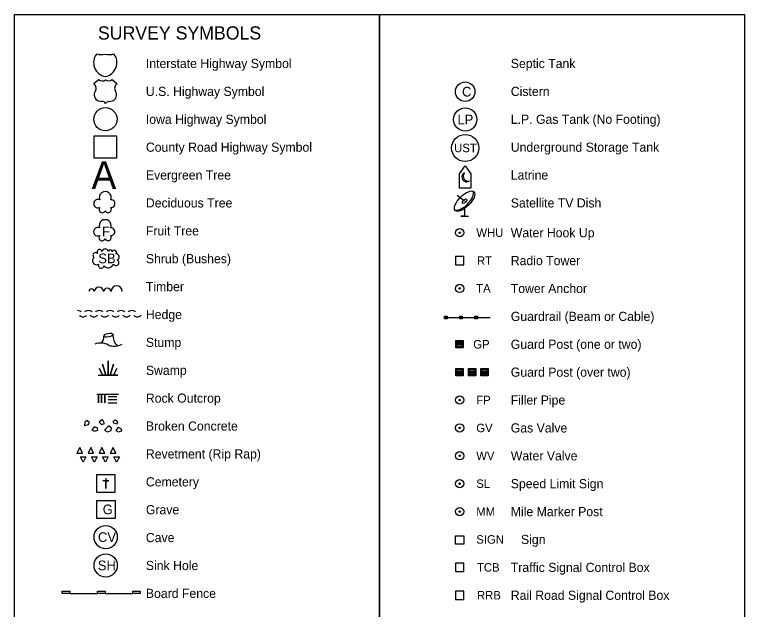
# Model space of a CAD drawing. Extents: x 6082259 to 6083454, y 5964102 to 5966092.
# Drawn here: x 6082259 to 6083454, y 5965119 to 5966092 of the extents above; entities that cross this region are included whole.
import ezdxf

# ---------------------------------------------------------------- set-up
doc = ezdxf.new("R2010")
doc.units = 0
for name, color, linetype in [('Default', 7, 'Continuous'), ('Level 20', 7, 'Continuous'), ('Text', 7, 'Continuous')]:
    doc.layers.add(name, color=color, linetype=linetype)

msp = doc.modelspace()

# ---------------------------------------------------------------- linework, layer by layer
at = {"layer": 'Default'}
for points in [[(6082259, 5966092.2), (6082856.5, 5966092.2), (6082856.5, 5964102.2), (6082259, 5964102.2)], [(6082856.5, 5966092.2), (6083454, 5966092.2), (6083454, 5964102.2), (6082856.5, 5964102.2)]]:
    msp.add_lwpolyline(points, close=True, dxfattribs=at)
at = {"layer": 'Level 20'}
for p, q in [((6082407.8, 5966012.2), (6082407.8, 5966012.2)), ((6082388.5, 5965978.8), (6082396.6, 5965986)), ((6082418.8, 5965985.9), (6082426.9, 5965978.7)), ((6082391, 5965966.7), (6082391.4, 5965967.3)), ((6082407.8, 5965966.5), (6082407.8, 5965966.5)), ((6082396.7, 5965951), (6082396, 5965951.3)), ((6082402.5, 5965950.1), (6082401.5, 5965950.1)), ((6082407.8, 5965920.9), (6082407.8, 5965920.9)), ((6082995.9, 5965786.9), (6082983.5, 5965796.2)), ((6082412.3, 5965467.3), (6082426.5, 5965467.3)), ((6082412.3, 5965462), (6082426.5, 5965462)), ((6082412.3, 5965456.6), (6082426.5, 5965456.6))]:
    msp.add_line(p, q, dxfattribs=at)
for points in [[(6082389.5, 5965893.5), (6082426, 5965893.5), (6082426, 5965857), (6082389.5, 5965857), (6082389.5, 5965893.5)], [(6082987.8, 5965808.3), (6082987.8, 5965831.8), (6082996.9, 5965844.5), (6083005.9, 5965831.8), (6083005.9, 5965808.3), (6082987.8, 5965808.3)], [(6082995.9, 5965774.5), (6082995.9, 5965762.1), (6082989.7, 5965762.1), (6083002.1, 5965762.1)], [(6082987.8, 5965682.8), (6082987.8, 5965682.8), (6082994.6, 5965682.8), (6082994.6, 5965696.4), (6082981, 5965696.4), (6082981, 5965682.8), (6082987.8, 5965682.8)], [(6082963.2, 5965594.3), (6082963.2, 5965598.4), (6082967.3, 5965598.4), (6082967.3, 5965594.3), (6082963.2, 5965594.3), (6082963.2, 5965595.7), (6082967.3, 5965595.7), (6082967.3, 5965597), (6082963.2, 5965597)], [(6082963.2, 5965596.4), (6083037.5, 5965596.4)], [(6082988, 5965594.3), (6082988, 5965598.4), (6082992.1, 5965598.4), (6082992.1, 5965594.3), (6082988, 5965594.3), (6082988, 5965595.7), (6082992.1, 5965595.7), (6082992.1, 5965597), (6082988, 5965597)], [(6083012.7, 5965594.3), (6083012.7, 5965598.4), (6083016.9, 5965598.4), (6083016.9, 5965594.3), (6083012.7, 5965594.3), (6083012.7, 5965595.7), (6083016.9, 5965595.7), (6083016.9, 5965597), (6083012.7, 5965597)], [(6082982.8, 5965547.7), (6082982.8, 5965557.6), (6082992.7, 5965557.6), (6082992.7, 5965547.7), (6082982.8, 5965547.7), (6082982.8, 5965549.7), (6082992.7, 5965549.7), (6082992.7, 5965551.7), (6082982.8, 5965551.7), (6082982.8, 5965553.7), (6082992.7, 5965553.7), (6082992.7, 5965555.6), (6082982.8, 5965555.6)], [(6082396, 5965502.1), (6082428.1, 5965502.1), (6082421, 5965502.1), (6082426.3, 5965512.8), (6082421, 5965502.1), (6082415.6, 5965502.1), (6082421, 5965520), (6082415.6, 5965502.1), (6082412.1, 5965502.1), (6082412.1, 5965525.3), (6082412.1, 5965502.1), (6082408.5, 5965502.1), (6082403.2, 5965520), (6082408.5, 5965502.1), (6082403.2, 5965502.1), (6082397.8, 5965512.8), (6082403.2, 5965502.1)], [(6082982.8, 5965502.1), (6082982.8, 5965512), (6082992.7, 5965512), (6082992.7, 5965502.1), (6082982.8, 5965502.1), (6082982.8, 5965504.1), (6082992.7, 5965504.1), (6082992.7, 5965506), (6082982.8, 5965506), (6082982.8, 5965508), (6082992.7, 5965508), (6082992.7, 5965510), (6082982.8, 5965510)], [(6083003.2, 5965502.1), (6083003.2, 5965512), (6083013.1, 5965512), (6083013.1, 5965502.1), (6083003.2, 5965502.1), (6083003.2, 5965504.1), (6083013.1, 5965504.1), (6083013.1, 5965506), (6083003.2, 5965506), (6083003.2, 5965508), (6083013.1, 5965508), (6083013.1, 5965510), (6083003.2, 5965510)], [(6083023.5, 5965502.1), (6083023.5, 5965512), (6083033.4, 5965512), (6083033.4, 5965502.1), (6083023.5, 5965502.1), (6083023.5, 5965504.1), (6083033.4, 5965504.1), (6083033.4, 5965506), (6083023.5, 5965506), (6083023.5, 5965508), (6083033.4, 5965508), (6083033.4, 5965510), (6083023.5, 5965510)], [(6082393.5, 5965470.9), (6082396.2, 5965470.9), (6082396.2, 5965456.6), (6082396.2, 5965470.9), (6082401.6, 5965470.9), (6082401.6, 5965456.6), (6082401.6, 5965470.9), (6082406.9, 5965470.9), (6082406.9, 5965456.6), (6082406.9, 5965470.9), (6082429.2, 5965470.9)], [(6082361, 5965374.6), (6082370.2, 5965374.6), (6082365.6, 5965383.8), (6082361, 5965374.6)], [(6082379.3, 5965374.6), (6082388.4, 5965374.6), (6082383.9, 5965383.8), (6082379.3, 5965374.6)], [(6082397.6, 5965374.6), (6082406.7, 5965374.6), (6082402.1, 5965383.8), (6082397.6, 5965374.6)], [(6082415.8, 5965374.6), (6082424.9, 5965374.6), (6082420.4, 5965383.8), (6082415.8, 5965374.6)], [(6082366.7, 5965368.6), (6082375.8, 5965368.6), (6082371.2, 5965359.5), (6082366.7, 5965368.6)], [(6082384.9, 5965368.6), (6082394.1, 5965368.6), (6082389.5, 5965359.5), (6082384.9, 5965368.6)], [(6082403.2, 5965368.6), (6082412.3, 5965368.6), (6082407.8, 5965359.5), (6082403.2, 5965368.6)], [(6082421.5, 5965368.6), (6082430.6, 5965368.6), (6082426, 5965359.5), (6082421.5, 5965368.6)], [(6082393.8, 5965310.2), (6082393.8, 5965339.7), (6082423.4, 5965339.7), (6082423.4, 5965310.2), (6082393.8, 5965310.2)], [(6082408.6, 5965333.3), (6082408.6, 5965316.6), (6082408.6, 5965328.9), (6082413.5, 5965328.9), (6082403.7, 5965328.9)], [(6082987.8, 5965180.8), (6082987.8, 5965180.8), (6082994.6, 5965180.8), (6082994.6, 5965194.3), (6082981, 5965194.3), (6082981, 5965180.8), (6082987.8, 5965180.8)], [(6082349.4, 5965145), (6082395, 5965145)], [(6082407.2, 5965145), (6082452.8, 5965145)], [(6082464.9, 5965145), (6082464.9, 5965145)], [(6082987.8, 5965135.1), (6082987.8, 5965135.1), (6082994.6, 5965135.1), (6082994.6, 5965148.7), (6082981, 5965148.7), (6082981, 5965135.1), (6082987.8, 5965135.1)]]:
    msp.add_lwpolyline(points, dxfattribs=at)
for points in [[(6082981.8, 5965546.7), (6082981.8, 5965558.6), (6082993.7, 5965558.6), (6082993.7, 5965546.7)], [(6082981.8, 5965501.1), (6082981.8, 5965513), (6082993.7, 5965513), (6082993.7, 5965501.1)], [(6083002.2, 5965501.1), (6083002.2, 5965513), (6083014.1, 5965513), (6083014.1, 5965501.1)], [(6083022.5, 5965501.1), (6083022.5, 5965513), (6083034.4, 5965513), (6083034.4, 5965501.1)], [(6082401.7, 5965429), (6082397.3, 5965424.9), (6082401.5, 5965421.3), (6082406.4, 5965422.8), (6082404.3, 5965427.2)], [(6082423.7, 5965428.6), (6082419.9, 5965426.3), (6082421.1, 5965424.2), (6082427.1, 5965422.6), (6082427.9, 5965425.5)], [(6082376.8, 5965427.8), (6082374.2, 5965425.4), (6082373.7, 5965419.7), (6082380.2, 5965421.3), (6082381.5, 5965424.9), (6082379.7, 5965426.2)], [(6082389.2, 5965417.2), (6082385.6, 5965412.5), (6082389.8, 5965410.4), (6082395.5, 5965412.3), (6082394.9, 5965415.1), (6082391.3, 5965417.2)], [(6082413.2, 5965419), (6082406, 5965411.8), (6082410.9, 5965409.4), (6082417.4, 5965411.3), (6082417.6, 5965415.4)], [(6082428.2, 5965416), (6082424.6, 5965411.4), (6082428.7, 5965409.3), (6082434.4, 5965411.1), (6082433.9, 5965413.9), (6082430.3, 5965416)], [(6082393.7, 5965267.5), (6082393.7, 5965297.2), (6082423.5, 5965297.2), (6082423.5, 5965267.5)], [(6082981, 5965225.7), (6082981, 5965239.2), (6082994.6, 5965239.2), (6082994.6, 5965225.7)], [(6082337.2, 5965145), (6082337.2, 5965148.4), (6082349.4, 5965148.4), (6082349.4, 5965145)], [(6082395, 5965145), (6082395, 5965148.4), (6082407.2, 5965148.4), (6082407.2, 5965145)], [(6082452.8, 5965145), (6082452.8, 5965148.4), (6082464.9, 5965148.4), (6082464.9, 5965145)]]:
    msp.add_lwpolyline(points, close=True, dxfattribs=at)
for centre, radius in [((6082996.8, 5965966), 16), ((6082407.8, 5965920.9), 19), ((6082996.9, 5965920.5), 19), ((6082996.9, 5965873.9), 22.2), ((6082987.8, 5965735.2), 6.79), ((6082987.8, 5965735.2), 1.13), ((6082987.8, 5965644), 6.79), ((6082987.8, 5965644), 1.13), ((6082987.8, 5965461.4), 6.79), ((6082987.8, 5965461.4), 1.13), ((6082987.8, 5965415.8), 6.79), ((6082987.8, 5965415.8), 1.13), ((6082987.8, 5965370.1), 6.79), ((6082987.8, 5965370.1), 1.13), ((6082987.8, 5965324.5), 6.79), ((6082987.8, 5965324.5), 1.13), ((6082987.8, 5965278.8), 6.79), ((6082987.8, 5965278.8), 1.13), ((6082408.2, 5965237), 19), ((6082408.2, 5965190.7), 19)]:
    msp.add_circle(centre, radius, dxfattribs=at)
for centre, radius, start, end in [((6082411.4, 5966013.6), 23, 141.2897, 260.377), ((6082401.1, 5966050), 23.3, 250.8344, 286.0898), ((6082414, 5966050), 23.3, 253.9102, 289.1613), ((6082403.7, 5966013.6), 23, 279.623, 38.7204), ((6082414, 5966050), 23.3, 289.1818, 289.185), ((6082384.1, 5965971.6), 8.46, 328.1178, 58.4185), ((6082402.4, 5965992.1), 8.46, 226.652, 308.6604), ((6082413, 5965992.1), 8.46, 230.5703, 313.348), ((6082431.3, 5965971.5), 8.46, 121.5815, 211.8822), ((6082399.6, 5965961), 10.3, 145.8972, 250.3585), ((6082415.8, 5965960.9), 10.3, 289.6415, 34.1028), ((6082403.5, 5965974.1), 24.1, 253.4797, 265.7777), ((6082402.1, 5965943), 7.07, 33.6844, 87.4407), ((6082413.9, 5965942.9), 7.07, 95.8567, 146.3156), ((6082411.9, 5965974.1), 24.1, 274.6642, 286.5203), ((6082999.3, 5965826.4), 7.87, 116.2289, 304.7925), ((6083001.5, 5965827.5), 7.91, 142.8907, 286.2253), ((6082407.5, 5965792.7), 9.75, 338.2051, 201.7949), ((6082395.5, 5965782.8), 6.97, 65.4824, 294.5175), ((6082417, 5965782.8), 6.36, 265.9982, 94.0018), ((6082402.6, 5965773.2), 5.31, 142.7501, 335.3223), ((6082412.2, 5965773.4), 5.3, 206.5242, 35.4033), ((6082407.3, 5965746.8), 9.75, 338.2051, 201.7949), ((6082395.4, 5965736.8), 6.97, 65.4824, 294.5175), ((6082416.8, 5965736.8), 6.36, 265.9982, 94.0018), ((6082402.5, 5965727.3), 5.31, 142.7501, 335.3223), ((6082412.1, 5965727.4), 5.3, 206.5242, 35.4033), ((6082398.1, 5965703.7), 4.12, 10.5948, 214.3611), ((6082407.6, 5965703.1), 5.57, 22.6036, 165.7836), ((6082415.7, 5965704.1), 3.15, 0.4605, 158.7839), ((6082422.3, 5965703.3), 3.57, 311.3936, 166.4114), ((6082393.2, 5965689.4), 6.62, 125.8289, 299.2848), ((6082391.7, 5965698.3), 4.32, 45.3455, 236.8073), ((6082425, 5965695.5), 5.15, 290.9039, 94.3687), ((6082400.8, 5965681.8), 4.68, 157.0258, 349.7602), ((6082412.2, 5965686.7), 8.99, 220.0183, 343.6977), ((6082425.2, 5965686.2), 4.79, 204.8294, 69.8871), ((6082397.2, 5965638.4), 7.66, 5.6097, 174.3903), ((6082410.9, 5965638.4), 6.15, 6.8184, 173.1816), ((6082426.2, 5965639.2), 9.15, 0, 180), ((6082385, 5965638.5), 4.63, 8.8069, 171.1931), ((6082388.6, 5965565.5), 16.7, 319.4836, 1.8241), ((6082444, 5965567.1), 24, 175.4776, 225.2691), ((6082400.1, 5965530.5), 24.2, 58.6739, 113.6979), ((6082422.1, 5965578.6), 29, 251.1942, 296.4339)]:
    msp.add_arc(centre, radius, start, end, dxfattribs=at)
for centre, major_axis, ratio in [((6082995.9, 5965786.9), (-15.3, -15.3), 0.428571), ((6082995.9, 5965786.9), (-3.28, -3.28), 0.5), ((6082412.7, 5965567.5), (-7.43, -1.49), 0.385758)]:
    msp.add_ellipse(centre, major_axis=major_axis, ratio=ratio, dxfattribs=at)
for centre, major_axis, ratio, start_param, end_param in [((6082994.1, 5965788.6), (-15.3, -15.3), 0.428571, 0.159141, 2.993624), ((6082362.1, 5965605.4), (5.94, 0), 0.4, 0, 1.570796), ((6082379.9, 5965605.4), (-5.94, 0), 0.4, 4.712389, 6.283185), ((6082379.9, 5965605.4), (5.94, 0), 0.4, 0, 1.570796), ((6082397.7, 5965605.4), (-5.94, 0), 0.4, 4.712389, 6.283185), ((6082397.7, 5965605.4), (5.94, 0), 0.4, 0, 1.570796), ((6082415.5, 5965605.4), (-5.94, 0), 0.4, 4.712389, 6.283185), ((6082415.5, 5965605.4), (5.94, 0), 0.4, 0, 1.570796), ((6082433.4, 5965605.4), (-5.94, 0), 0.4, 4.712389, 6.283185), ((6082433.4, 5965605.4), (5.94, 0), 0.4, 0, 1.570796), ((6082451.2, 5965605.4), (-5.94, 0), 0.4, 4.712389, 6.283185), ((6082451.2, 5965605.4), (5.94, 0), 0.4, 0, 1.570796), ((6082371, 5965600.1), (-5.94, 0), 0.4, 0, 3.141593), ((6082388.8, 5965600.1), (-5.94, 0), 0.4, 0, 3.141593), ((6082406.6, 5965600.1), (-5.94, 0), 0.4, 0, 3.141593), ((6082424.5, 5965600.1), (-5.94, 0), 0.4, 0, 3.141593), ((6082442.3, 5965600.1), (-5.94, 0), 0.4, 0, 3.141593), ((6082460.1, 5965600.1), (-5.94, 0), 0.4, 0, 3.141593)]:
    msp.add_ellipse(centre, major_axis=major_axis, ratio=ratio, start_param=start_param, end_param=end_param, dxfattribs=at)

# ---------------------------------------------------------------- texts
for s, height, p in [('C', 15.8, (6082991.7, 5965958.1)), ('LP', 15.85, (6082984.3, 5965912.5)), ('UST', 13.87, (6082978.8, 5965867)), ('A', 45.3, (6082385.1, 5965807)), ('F', 15.8, (6082402.3, 5965729.3)), ('WHU', 13.82, (6083015.2, 5965728.3)), ('SB', 15.85, (6082396.1, 5965685.3)), ('RT', 13.87, (6083016.1, 5965682.7)), ('TA', 13.93, (6083014.8, 5965637.2)), ('GP', 13.87, (6083010, 5965545.7)), ('FP', 13.82, (6083015, 5965454.5)), ('GV', 13.82, (6083015, 5965408.8)), ('WV', 13.82, (6083015, 5965363.2)), ('SL', 13.82, (6083015, 5965317.6)), ('G', 15.8, (6082403.4, 5965274.5)), ('MM', 13.82, (6083015, 5965271.9)), ('CV', 15.85, (6082395.6, 5965229.1)), ('Cave', 15, (6082474, 5965228.8)), ('SIGN', 13.87, (6083015, 5965226.3)), ('Sign', 15, (6083088.2, 5965225.7)), ('SH', 15.85, (6082395.3, 5965182.8)), ('TCB', 13.87, (6083016.1, 5965180.6)), ('RRB', 13.87, (6083016.1, 5965135))]:
    msp.add_text(s, height=height, dxfattribs=at).set_placement(p)
at = {"layer": 'Text'}
for s, height, p in [('SURVEY SYMBOLS', 21.667, (6082395.5, 5966051.3)), ('Interstate Highway Symbol', 15, (6082474, 5966004.7)), ('Septic Tank', 15, (6083071.5, 5966004.7)), ('U.S. Highway Symbol', 15, (6082474, 5965959)), ('Cistern', 15, (6083071.5, 5965959)), ('Iowa Highway Symbol', 15, (6082474, 5965913.4)), ('L.P. Gas Tank (No Footing)', 15, (6083071.5, 5965913.4)), ('County Road Highway Symbol', 15, (6082474, 5965867.7)), ('Underground Storage Tank', 15, (6083071.5, 5965867.7)), ('Evergreen Tree', 15, (6082474, 5965822.1)), ('Latrine', 15, (6083071.5, 5965822.1)), ('Deciduous Tree', 15, (6082474, 5965776.5)), ('Satellite TV Dish', 15, (6083071.5, 5965776.5)), ('Fruit Tree', 15, (6082474, 5965730.8)), ('Water Hook Up', 15, (6083071.5, 5965727.7)), ('Shrub (Bushes)', 15, (6082474, 5965685.2)), ('Radio Tower', 15, (6083071.5, 5965682.1)), ('Timber', 15, (6082474, 5965639.5)), ('Tower Anchor', 15, (6083071.5, 5965636.5)), ('Hedge', 15, (6082474, 5965593.9)), ('Guardrail (Beam or Cable)', 15, (6083071.5, 5965590.8)), ('Stump', 15, (6082474, 5965548.2)), ('Guard Post (one or two)', 15, (6083071.5, 5965545.2)), ('Swamp', 15, (6082474, 5965502.6)), ('Guard Post (over two)', 15, (6083071.5, 5965499.5)), ('Rock Outcrop', 15, (6082474, 5965457)), ('Filler Pipe', 15, (6083071.5, 5965453.9)), ('Broken Concrete', 15, (6082474, 5965411.3)), ('Gas Valve', 15, (6083071.5, 5965408.3)), ('Revetment (Rip Rap)', 15, (6082474, 5965365.7)), ('Water Valve', 15, (6083071.5, 5965362.6)), ('Cemetery', 15, (6082474, 5965320)), ('Speed Limit Sign', 15, (6083071.5, 5965317)), ('Grave', 15, (6082474, 5965274.4)), ('Mile Marker Post', 15, (6083071.5, 5965271.3)), ('Sink Hole', 15, (6082474, 5965183.1)), ('Traffic Signal Control Box', 15, (6083071.5, 5965180)), ('Board Fence', 15, (6082474, 5965137.5)), ('Rail Road Signal Control Box', 15, (6083071.5, 5965134.4))]:
    msp.add_text(s, height=height, dxfattribs=at).set_placement(p)

doc.saveas('drawing.dxf')
